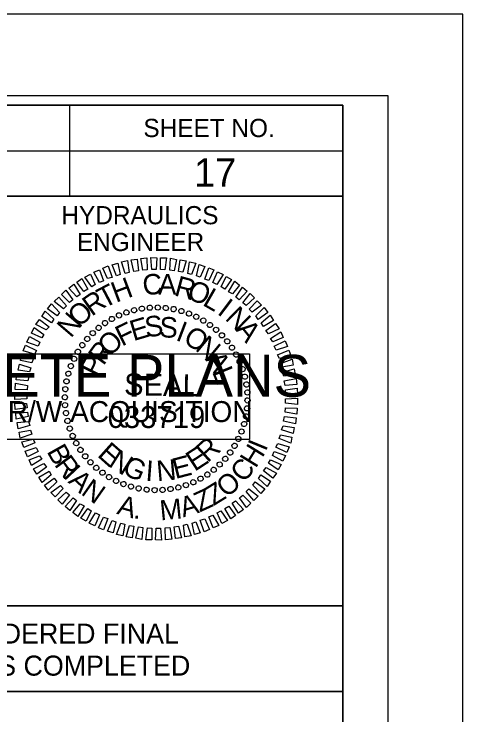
# Model space of a CAD drawing. Extents: x 1779926 to 1781626, y 618464 to 619564.
# Drawn here: x 1781502.8 to 1781626, y 619371.7 to 619564.2 of the extents above; entities that cross this region are included whole.
import ezdxf

# ---------------------------------------------------------------- set-up
doc = ezdxf.new("R2010")
doc.units = 0
for name, color, linetype in [('Old_Level_58', 7, 'Continuous'), ('Sheet Data Field CELL', 7, 'Continuous'), ('Sheet Plot Border Inside CELL', 7, 'Continuous'), ('Sheet Plot Border Outside CELL', 7, 'Continuous'), ('Sheet Professional Seal CELL', 7, 'Continuous'), ('Sheet Profile CELL', 7, 'Continuous'), ('Sheet Profile Grid Major CELL', 7, 'Continuous'), ('Sheet Profile Grid Minor CELL', 7, 'Continuous'), ('Sheet Sticker Exception Certification CELL', 7, 'Continuous'), ('Sheet Sticker Incomplete CELL', 7, 'Continuous')]:
    doc.layers.add(name, color=color, linetype=linetype)

msp = doc.modelspace()

# ---------------------------------------------------------------- linework, layer by layer
at = {"layer": 'Old_Level_58'}
for points in [[(1781392.9, 619378.14), (1781592.96, 619378.14), (1781592.96, 619314.19), (1781392.9, 619314.19)], [(1781392.96, 619378.14), (1781592.96, 619378.14), (1781592.96, 619314.19), (1781392.96, 619314.19)]]:
    msp.add_lwpolyline(points, close=True, dxfattribs=at)
at = {"layer": 'Sheet Plot Border Inside CELL'}
msp.add_lwpolyline([(1779938.96, 618486.64), (1781605.46, 618486.64), (1781605.46, 619541.74), (1779938.96, 619541.74)], close=True, dxfattribs=at)
at = {"layer": 'Sheet Plot Border Outside CELL'}
msp.add_lwpolyline([(1779925.96, 618464.19), (1781625.96, 618464.19), (1781625.96, 619564.19), (1779925.96, 619564.19)], close=True, dxfattribs=at)
at = {"layer": 'Sheet Professional Seal CELL'}
for p, q in [((1781535.68, 619482.87), (1781535.68, 619482.87)), ((1781537.88, 619483.27), (1781537.88, 619483.27)), ((1781540.03, 619483.57), (1781540.03, 619483.57)), ((1781542.23, 619483.62), (1781542.23, 619483.62)), ((1781544.43, 619483.47), (1781544.43, 619483.47)), ((1781546.58, 619483.12), (1781546.58, 619483.12)), ((1781548.68, 619482.67), (1781548.68, 619482.67)), ((1781529.63, 619480.47), (1781529.63, 619480.47)), ((1781531.58, 619481.47), (1781531.58, 619481.47)), ((1781533.58, 619482.27), (1781533.58, 619482.27)), ((1781550.78, 619481.97), (1781550.78, 619481.97)), ((1781552.78, 619481.07), (1781552.78, 619481.07)), ((1781527.73, 619479.32), (1781527.73, 619479.32)), ((1781554.73, 619480.07), (1781554.73, 619480.07)), ((1781556.53, 619478.82), (1781556.53, 619478.82)), ((1781524.33, 619476.57), (1781524.33, 619476.57)), ((1781525.98, 619478.07), (1781525.98, 619478.07)), ((1781558.28, 619477.47), (1781558.28, 619477.47)), ((1781522.83, 619475.02), (1781522.83, 619475.02)), ((1781559.83, 619475.97), (1781559.83, 619475.97)), ((1781521.48, 619473.27), (1781521.48, 619473.27)), ((1781561.33, 619474.32), (1781561.33, 619474.32)), ((1781520.23, 619471.47), (1781520.23, 619471.47)), ((1781562.58, 619472.57), (1781562.58, 619472.57)), ((1781519.23, 619469.52), (1781519.23, 619469.52)), ((1781563.73, 619470.67), (1781563.73, 619470.67)), ((1781518.33, 619467.52), (1781518.33, 619467.52)), ((1781564.73, 619468.72), (1781564.73, 619468.72)), ((1781517.63, 619465.42), (1781517.63, 619465.42)), ((1781565.53, 619466.72), (1781565.53, 619466.72)), ((1781517.18, 619463.32), (1781517.18, 619463.32)), ((1781566.13, 619464.62), (1781566.13, 619464.62)), ((1781516.83, 619461.17), (1781516.83, 619461.17)), ((1781566.53, 619462.42), (1781566.53, 619462.42)), ((1781566.83, 619460.27), (1781566.83, 619460.27)), ((1781516.68, 619458.97), (1781516.68, 619458.97)), ((1781541.78, 619458.52), (1781541.78, 619458.52)), ((1781566.88, 619458.07), (1781566.88, 619458.07)), ((1781516.73, 619456.77), (1781516.73, 619456.77)), ((1781566.73, 619455.87), (1781566.73, 619455.87)), ((1781517.03, 619454.62), (1781517.03, 619454.62)), ((1781566.38, 619453.72), (1781566.38, 619453.72)), ((1781517.43, 619452.42), (1781517.43, 619452.42)), ((1781565.93, 619451.62), (1781565.93, 619451.62)), ((1781518.03, 619450.32), (1781518.03, 619450.32)), ((1781518.83, 619448.32), (1781518.83, 619448.32)), ((1781565.23, 619449.52), (1781565.23, 619449.52)), ((1781519.83, 619446.37), (1781519.83, 619446.37)), ((1781564.33, 619447.52), (1781564.33, 619447.52)), ((1781520.98, 619444.47), (1781520.98, 619444.47)), ((1781563.33, 619445.57), (1781563.33, 619445.57)), ((1781522.23, 619442.72), (1781522.23, 619442.72)), ((1781560.73, 619442.02), (1781560.73, 619442.02)), ((1781562.08, 619443.77), (1781562.08, 619443.77)), ((1781523.73, 619441.07), (1781523.73, 619441.07)), ((1781559.23, 619440.47), (1781559.23, 619440.47)), ((1781525.28, 619439.57), (1781525.28, 619439.57)), ((1781527.03, 619438.22), (1781527.03, 619438.22)), ((1781557.58, 619438.97), (1781557.58, 619438.97)), ((1781528.83, 619436.97), (1781528.83, 619436.97)), ((1781553.93, 619436.57), (1781553.93, 619436.57)), ((1781555.83, 619437.72), (1781555.83, 619437.72)), ((1781530.78, 619435.97), (1781530.78, 619435.97)), ((1781532.78, 619435.07), (1781532.78, 619435.07)), ((1781534.88, 619434.37), (1781534.88, 619434.37)), ((1781549.98, 619434.77), (1781549.98, 619434.77)), ((1781551.98, 619435.57), (1781551.98, 619435.57)), ((1781536.98, 619433.92), (1781536.98, 619433.92)), ((1781539.13, 619433.57), (1781539.13, 619433.57)), ((1781541.33, 619433.42), (1781541.33, 619433.42)), ((1781543.53, 619433.47), (1781543.53, 619433.47)), ((1781545.68, 619433.77), (1781545.68, 619433.77)), ((1781547.88, 619434.17), (1781547.88, 619434.17))]:
    msp.add_line(p, q, dxfattribs=at)
for points in [[(1781533.28, 619492.97), (1781532.23, 619496.12), (1781533.93, 619496.47), (1781534.33, 619493.22)], [(1781535.68, 619493.52), (1781534.88, 619496.72), (1781536.53, 619496.87), (1781536.88, 619493.67)], [(1781538.08, 619493.82), (1781537.53, 619497.02), (1781539.23, 619497.22), (1781539.28, 619493.97)], [(1781540.58, 619494.07), (1781540.33, 619497.32), (1781541.98, 619497.27), (1781541.78, 619494.02)], [(1781542.98, 619494.02), (1781542.98, 619497.27), (1781544.63, 619497.22), (1781544.18, 619493.97)], [(1781545.48, 619493.87), (1781545.68, 619497.12), (1781547.33, 619496.82), (1781546.68, 619493.67)], [(1781547.88, 619493.47), (1781548.33, 619496.67), (1781549.98, 619496.42), (1781549.08, 619493.32)], [(1781550.43, 619492.92), (1781550.93, 619496.17), (1781552.63, 619495.77), (1781551.48, 619492.67)], [(1781526.23, 619490.47), (1781524.63, 619493.27), (1781526.18, 619493.97), (1781527.33, 619490.92)], [(1781528.43, 619491.52), (1781527.13, 619494.42), (1781528.63, 619495.02), (1781529.68, 619491.82)], [(1781530.88, 619492.32), (1781529.73, 619495.32), (1781531.28, 619495.77), (1781531.93, 619492.67)], [(1781552.83, 619492.27), (1781553.58, 619495.37), (1781555.13, 619494.87), (1781553.88, 619491.92)], [(1781555.08, 619491.37), (1781556.23, 619494.52), (1781557.63, 619493.92), (1781556.23, 619491.02)], [(1781524.08, 619489.27), (1781522.23, 619491.97), (1781523.78, 619492.77), (1781525.03, 619489.87)], [(1781557.33, 619490.42), (1781558.58, 619493.37), (1781560.13, 619492.67), (1781558.43, 619489.87)], [(1781559.63, 619489.27), (1781560.98, 619492.12), (1781562.48, 619491.27), (1781560.58, 619488.67)], [(1781521.88, 619488.02), (1781520.03, 619490.57), (1781521.33, 619491.52), (1781522.98, 619488.62)], [(1781561.58, 619487.92), (1781563.33, 619490.82), (1781564.63, 619489.77), (1781562.68, 619487.32)], [(1781517.98, 619484.97), (1781515.78, 619487.17), (1781516.98, 619488.37), (1781518.93, 619485.67)], [(1781519.98, 619486.52), (1781517.83, 619488.92), (1781519.18, 619489.97), (1781520.93, 619487.17)], [(1781563.63, 619486.42), (1781565.48, 619489.17), (1781566.78, 619488.07), (1781564.58, 619485.72)], [(1781516.33, 619483.22), (1781513.78, 619485.27), (1781515.03, 619486.42), (1781517.13, 619484.02)], [(1781565.53, 619484.87), (1781567.58, 619487.47), (1781568.78, 619486.27), (1781566.48, 619484.12)], [(1781514.58, 619481.32), (1781511.98, 619483.27), (1781513.08, 619484.57), (1781515.28, 619482.22)], [(1781567.33, 619483.12), (1781569.48, 619485.47), (1781570.68, 619484.27), (1781568.08, 619482.32)], [(1781513.08, 619479.42), (1781510.38, 619481.12), (1781511.33, 619482.57), (1781513.73, 619480.37)], [(1781569.08, 619481.32), (1781571.38, 619483.57), (1781572.43, 619482.22), (1781569.78, 619480.32)], [(1781570.58, 619479.37), (1781573.03, 619481.47), (1781573.98, 619480.02), (1781571.18, 619478.42)], [(1781511.58, 619477.42), (1781508.78, 619478.92), (1781509.78, 619480.32), (1781512.38, 619478.32)], [(1781571.88, 619477.32), (1781574.53, 619479.22), (1781575.48, 619477.72), (1781572.58, 619476.32)], [(1781510.38, 619475.27), (1781507.53, 619476.52), (1781508.28, 619478.07), (1781510.98, 619476.22)], [(1781573.18, 619475.12), (1781575.98, 619476.87), (1781576.63, 619475.32), (1781573.78, 619474.17)], [(1781509.38, 619472.97), (1781506.28, 619474.12), (1781507.03, 619475.67), (1781509.88, 619474.07)], [(1781508.38, 619470.77), (1781505.28, 619471.67), (1781505.93, 619473.22), (1781508.93, 619471.82)], [(1781574.18, 619472.97), (1781577.13, 619474.47), (1781577.78, 619472.87), (1781574.68, 619471.87)], [(1781575.08, 619470.62), (1781578.13, 619471.92), (1781578.68, 619470.37), (1781575.58, 619469.57)], [(1781507.63, 619468.37), (1781504.53, 619469.02), (1781504.88, 619470.67), (1781508.03, 619469.42)], [(1781575.88, 619468.22), (1781579.08, 619469.37), (1781579.38, 619467.72), (1781576.23, 619467.17)], [(1781506.98, 619465.97), (1781503.88, 619466.37), (1781504.23, 619468.07), (1781507.38, 619467.02)], [(1781506.58, 619463.42), (1781503.38, 619463.72), (1781503.58, 619465.42), (1781506.83, 619464.62)], [(1781576.48, 619465.82), (1781579.63, 619466.77), (1781579.93, 619465.07), (1781576.78, 619464.77)], [(1781576.93, 619463.42), (1781580.18, 619464.12), (1781580.33, 619462.42), (1781577.13, 619462.22)], [(1781506.33, 619461.02), (1781503.08, 619461.12), (1781503.18, 619462.77), (1781506.43, 619462.22)], [(1781577.23, 619461.02), (1781580.48, 619461.42), (1781580.58, 619459.72), (1781577.33, 619459.82)], [(1781506.28, 619458.52), (1781503.03, 619458.37), (1781503.03, 619460.07), (1781506.28, 619459.72)], [(1781506.33, 619456.02), (1781503.08, 619455.62), (1781502.98, 619457.32), (1781506.23, 619457.22)], [(1781577.28, 619458.52), (1781580.53, 619458.67), (1781580.53, 619456.97), (1781577.28, 619457.32)], [(1781577.23, 619456.02), (1781580.48, 619455.92), (1781580.38, 619454.27), (1781577.13, 619454.82)], [(1781506.63, 619453.62), (1781503.38, 619452.92), (1781503.23, 619454.62), (1781506.43, 619454.82)], [(1781576.98, 619453.62), (1781580.18, 619453.32), (1781579.98, 619451.62), (1781576.73, 619452.42)], [(1781507.08, 619451.22), (1781503.93, 619450.27), (1781503.63, 619451.97), (1781506.78, 619452.27)], [(1781507.68, 619448.82), (1781504.48, 619447.67), (1781504.18, 619449.32), (1781507.33, 619449.87)], [(1781576.58, 619451.07), (1781579.68, 619450.67), (1781579.33, 619448.97), (1781576.18, 619450.02)], [(1781575.93, 619448.67), (1781579.03, 619448.02), (1781578.68, 619446.37), (1781575.53, 619447.62)], [(1781508.48, 619446.42), (1781505.43, 619445.12), (1781504.88, 619446.67), (1781507.98, 619447.47)], [(1781575.18, 619446.27), (1781578.28, 619445.37), (1781577.63, 619443.82), (1781574.63, 619445.22)], [(1781509.38, 619444.07), (1781506.43, 619442.57), (1781505.78, 619444.17), (1781508.88, 619445.17)], [(1781574.18, 619444.07), (1781577.28, 619442.92), (1781576.53, 619441.37), (1781573.68, 619442.97)], [(1781510.38, 619441.92), (1781507.58, 619440.17), (1781506.93, 619441.72), (1781509.78, 619442.87)], [(1781511.68, 619439.72), (1781509.03, 619437.82), (1781508.08, 619439.32), (1781510.98, 619440.72)], [(1781573.18, 619441.77), (1781576.03, 619440.52), (1781575.28, 619438.97), (1781572.58, 619440.82)], [(1781512.98, 619437.67), (1781510.53, 619435.57), (1781509.58, 619437.02), (1781512.38, 619438.62)], [(1781571.98, 619439.62), (1781574.78, 619438.12), (1781573.78, 619436.72), (1781571.18, 619438.72)], [(1781514.48, 619435.72), (1781512.18, 619433.47), (1781511.13, 619434.82), (1781513.78, 619436.72)], [(1781570.48, 619437.62), (1781573.18, 619435.92), (1781572.23, 619434.47), (1781569.83, 619436.67)], [(1781516.23, 619433.92), (1781514.08, 619431.57), (1781512.88, 619432.77), (1781515.48, 619434.72)], [(1781568.98, 619435.72), (1781571.58, 619433.77), (1781570.48, 619432.47), (1781568.28, 619434.82)], [(1781518.03, 619432.17), (1781515.98, 619429.57), (1781514.78, 619430.77), (1781517.08, 619432.92)], [(1781567.23, 619433.82), (1781569.78, 619431.77), (1781568.53, 619430.62), (1781566.43, 619433.02)], [(1781519.93, 619430.62), (1781518.08, 619427.87), (1781516.78, 619428.97), (1781518.98, 619431.32)], [(1781563.58, 619430.52), (1781565.73, 619428.12), (1781564.38, 619427.07), (1781562.63, 619429.87)], [(1781565.58, 619432.07), (1781567.78, 619429.87), (1781566.58, 619428.67), (1781564.63, 619431.37)], [(1781521.98, 619429.12), (1781520.23, 619426.22), (1781518.93, 619427.27), (1781520.88, 619429.72)], [(1781561.68, 619429.02), (1781563.53, 619426.47), (1781562.23, 619425.52), (1781560.58, 619428.42)], [(1781523.93, 619427.77), (1781522.58, 619424.92), (1781521.08, 619425.77), (1781522.98, 619428.37)], [(1781526.23, 619426.62), (1781524.98, 619423.67), (1781523.43, 619424.37), (1781525.13, 619427.17)], [(1781557.33, 619426.57), (1781558.93, 619423.77), (1781557.38, 619423.07), (1781556.23, 619426.12)], [(1781559.48, 619427.77), (1781561.33, 619425.07), (1781559.78, 619424.27), (1781558.53, 619427.17)], [(1781528.48, 619425.67), (1781527.33, 619422.52), (1781525.93, 619423.12), (1781527.33, 619426.02)], [(1781530.73, 619424.77), (1781529.98, 619421.67), (1781528.43, 619422.17), (1781529.68, 619425.12)], [(1781552.68, 619424.72), (1781553.83, 619421.72), (1781552.28, 619421.27), (1781551.63, 619424.37)], [(1781555.13, 619425.52), (1781556.43, 619422.62), (1781554.93, 619422.02), (1781553.88, 619425.22)], [(1781533.13, 619424.12), (1781532.63, 619420.87), (1781530.93, 619421.27), (1781532.08, 619424.37)], [(1781535.68, 619423.57), (1781535.23, 619420.37), (1781533.58, 619420.62), (1781534.48, 619423.72)], [(1781538.08, 619423.17), (1781537.88, 619419.92), (1781536.23, 619420.22), (1781536.88, 619423.37)], [(1781540.58, 619423.02), (1781540.58, 619419.77), (1781538.93, 619419.82), (1781539.38, 619423.07)], [(1781542.98, 619422.97), (1781543.23, 619419.72), (1781541.58, 619419.77), (1781541.78, 619423.02)], [(1781545.48, 619423.22), (1781546.03, 619420.02), (1781544.33, 619419.82), (1781544.28, 619423.07)], [(1781547.88, 619423.52), (1781548.68, 619420.32), (1781547.03, 619420.17), (1781546.68, 619423.37)], [(1781550.28, 619424.07), (1781551.33, 619420.92), (1781549.63, 619420.57), (1781549.23, 619423.82)]]:
    msp.add_lwpolyline(points, close=True, dxfattribs=at)
for centre, major_axis in [((1781540.03, 619483.54), (-0.05, 0.718)), ((1781542.22, 619483.59), (0.013, 0.72)), ((1781533.61, 619482.23), (-0.234, 0.681)), ((1781535.71, 619482.85), (-0.174, 0.699)), ((1781537.85, 619483.29), (-0.113, 0.711)), ((1781544.4, 619483.46), (0.075, 0.716)), ((1781546.56, 619483.14), (0.137, 0.707)), ((1781548.69, 619482.62), (0.198, 0.692)), ((1781550.77, 619481.93), (0.258, 0.672)), ((1781529.62, 619480.45), (-0.349, 0.63)), ((1781531.58, 619481.43), (-0.293, 0.658)), ((1781552.77, 619481.06), (0.316, 0.647)), ((1781554.69, 619480.01), (0.371, 0.617)), ((1781525.99, 619478.01), (-0.453, 0.56)), ((1781527.75, 619479.31), (-0.403, 0.597)), ((1781556.52, 619478.81), (0.423, 0.582)), ((1781524.36, 619476.56), (-0.5, 0.518)), ((1781558.23, 619477.44), (0.472, 0.543)), ((1781559.82, 619475.94), (0.518, 0.5)), ((1781522.85, 619474.97), (-0.543, 0.472)), ((1781561.27, 619474.3), (0.56, 0.453)), ((1781521.49, 619473.26), (-0.582, 0.423)), ((1781562.57, 619472.54), (0.597, 0.403)), ((1781520.28, 619471.43), (-0.617, 0.371)), ((1781563.71, 619470.68), (0.63, 0.349)), ((1781519.24, 619469.51), (-0.647, 0.316)), ((1781564.69, 619468.72), (0.658, 0.293)), ((1781518.36, 619467.5), (-0.672, 0.258)), ((1781565.49, 619466.68), (0.681, 0.234)), ((1781517.67, 619465.43), (-0.692, 0.198)), ((1781566.11, 619464.58), (0.699, 0.174)), ((1781517.16, 619463.3), (-0.707, 0.137)), ((1781566.55, 619462.44), (0.711, 0.113)), ((1781516.83, 619461.14), (-0.716, 0.075)), ((1781516.7, 619458.95), (-0.72, 0.013)), ((1781566.8, 619460.27), (0.718, 0.05)), ((1781516.76, 619456.77), (-0.718, -0.05)), ((1781566.85, 619458.08), (0.72, -0.013)), ((1781566.72, 619455.89), (0.716, -0.075)), ((1781517.01, 619454.59), (-0.711, -0.113)), ((1781566.4, 619453.73), (0.707, -0.137)), ((1781517.44, 619452.45), (-0.699, -0.174)), ((1781565.89, 619451.6), (0.692, -0.198)), ((1781518.06, 619450.35), (-0.681, -0.234)), ((1781565.19, 619449.53), (0.672, -0.258)), ((1781518.87, 619448.32), (-0.658, -0.293)), ((1781564.32, 619447.52), (0.647, -0.316)), ((1781519.84, 619446.36), (-0.63, -0.349)), ((1781563.28, 619445.6), (0.617, -0.371)), ((1781520.99, 619444.49), (-0.597, -0.403)), ((1781562.07, 619443.77), (0.582, -0.423)), ((1781522.29, 619442.73), (-0.56, -0.453)), ((1781560.71, 619442.06), (0.543, -0.472)), ((1781523.74, 619441.09), (-0.518, -0.5)), ((1781525.32, 619439.59), (-0.472, -0.543)), ((1781559.2, 619440.48), (0.5, -0.518)), ((1781527.04, 619438.23), (-0.423, -0.582)), ((1781555.8, 619437.72), (0.403, -0.597)), ((1781557.56, 619439.03), (0.453, -0.56)), ((1781528.86, 619437.02), (-0.371, -0.617)), ((1781530.78, 619435.97), (-0.316, -0.647)), ((1781551.98, 619435.6), (0.293, -0.658)), ((1781553.94, 619436.58), (0.349, -0.63)), ((1781532.79, 619435.1), (-0.258, -0.672)), ((1781534.86, 619434.41), (-0.198, -0.692)), ((1781536.99, 619433.9), (-0.137, -0.707)), ((1781539.16, 619433.57), (-0.075, -0.716)), ((1781543.53, 619433.5), (0.05, -0.718)), ((1781545.7, 619433.75), (0.113, -0.711)), ((1781547.84, 619434.18), (0.174, -0.699)), ((1781549.94, 619434.8), (0.234, -0.681)), ((1781541.34, 619433.44), (-0.013, -0.72))]:
    msp.add_ellipse(centre, major_axis=major_axis, ratio=0.999708, dxfattribs=at)
at = {"layer": 'Sheet Profile CELL'}
for p, q in [((1781517.96, 619539.14), (1781517.96, 619514.14)), ((1781392.91, 619526.64), (1781592.96, 619526.64))]:
    msp.add_line(p, q, dxfattribs=at)
for points in [[(1781592.96, 619539.19), (1780092.96, 619539.19), (1780092.96, 618489.19), (1781592.96, 618489.19)], [(1781392.91, 619539.19), (1781592.96, 619539.19), (1781592.96, 619514.14), (1781392.91, 619514.14)], [(1781492.96, 619514.14), (1781592.96, 619514.14), (1781592.96, 619401.64), (1781492.96, 619401.64)]]:
    msp.add_lwpolyline(points, close=True, dxfattribs=at)
at = {"layer": 'Sheet Profile Grid Major CELL'}
msp.add_lwpolyline([(1781542.96, 619314.19), (1781542.96, 619039.19), (1781592.96, 619039.19), (1781592.96, 619389.19)], dxfattribs=at)
at = {"layer": 'Sheet Sticker Exception Certification CELL'}
for p, q in [((1781392.91, 619401.64), (1781592.95, 619401.64)), ((1781392.91, 619401.64), (1781592.95, 619401.64)), ((1781592.95, 619401.63), (1781592.95, 619378.13)), ((1781592.95, 619401.63), (1781592.95, 619378.13)), ((1781592.95, 619378.14), (1781392.91, 619378.14)), ((1781592.95, 619378.14), (1781392.91, 619378.14))]:
    msp.add_line(p, q, dxfattribs=at)
at = {"layer": 'Sheet Sticker Incomplete CELL'}
msp.add_lwpolyline([(1781420.37, 619447.38), (1781420.37, 619470.88), (1781567.37, 619470.88), (1781567.37, 619447.38)], close=True, dxfattribs=at)

# ---------------------------------------------------------------- texts
at = {"layer": 'Sheet Data Field CELL'}
msp.add_text('17', height=7.75, dxfattribs=at).set_placement((1781552.18, 619516.8))
at = {"layer": 'Sheet Professional Seal CELL'}
for s, height, rotation, p in [('C', 5.64, 6.2199, (1781538.33, 619486.87)), ('A', 5.64, 359.0203, (1781542.28, 619487.17)), ('R', 5.64, 344.6211, (1781546.48, 619486.97)), ('T', 5.64, 27.8198, (1781527.48, 619483.22)), ('H', 5.64, 20.6195, (1781530.73, 619484.87)), ('O', 5.64, 337.4212, (1781549.83, 619486.22)), ('L', 5.64, 330.2209, (1781554.23, 619484.37)), ('R', 5.64, 35.0205, (1781524.08, 619481.02)), ('O', 5.64, 42.2217, (1781520.63, 619477.92)), ('I', 5.64, 323.0201, (1781558.28, 619481.97)), ('N', 5.64, 49.4235, (1781518.33, 619475.02)), ('N', 5.64, 315.8189, (1781560.43, 619480.42)), ('E', 5.64, 16.6111, (1781535.53, 619474.32)), ('S', 5.64, 7.2556, (1781538.98, 619475.37)), ('S', 5.64, 357.9004, (1781542.58, 619475.42)), ('F', 5.64, 25.967, (1781532.33, 619472.82)), ('I', 5.64, 339.1896, (1781546.88, 619474.72)), ('A', 5.64, 308.6172, (1781563.38, 619477.47)), ('O', 5.64, 44.6812, (1781529.03, 619469.87)), ('O', 5.64, 329.8335, (1781548.88, 619474.02)), ('N', 5.64, 320.4766, (1781552.23, 619472.02)), ('R', 5.64, 54.0397, (1781527.28, 619467.42)), ('P', 5.64, 63.3989, (1781525.68, 619464.22)), ('A', 5.64, 301.7603, (1781555.08, 619469.42)), ('L', 5.64, 292.4008, (1781557.03, 619465.97)), ('SEAL', 5.998, 359, (1781532.93, 619459.52)), ('E', 5.64, 318.2769, (1781525.38, 619442.87)), ('R', 5.64, 42.4814, (1781555.88, 619440.77)), ('N', 5.64, 327.634, (1781528.38, 619440.17)), ('E', 5.64, 33.1241, (1781552.33, 619438.42)), ('G', 5.64, 336.9902, (1781532.18, 619437.92)), ('N', 5.64, 5.0564, (1781542.08, 619435.87)), ('E', 5.64, 14.4118, (1781547.03, 619436.47)), ('I', 5.64, 355.7012, (1781538.73, 619436.02))]:
    msp.add_text(s, height=height, rotation=rotation, dxfattribs=at).set_placement(p)
at = {"layer": 'Sheet Profile CELL'}
for s, p in [('SHEET NO.', (1781538.27, 619530.4)), ('HYDRAULICS', (1781515.77, 619506.45)), ('ENGINEER', (1781520.02, 619499.1))]:
    msp.add_text(s, height=5, dxfattribs=at).set_placement(p)
at = {"layer": 'Sheet Profile Grid Minor CELL'}
msp.add_text('033719', height=5.998, dxfattribs=at).set_placement((1781528.46, 619450.51))
for s, rotation, p in [('B', 299.1529, (1781511.63, 619444.08)), ('H', 58.3478, (1781569.09, 619439.24)), ('I', 67.5926, (1781571.83, 619443.88)), ('R', 306.2797, (1781513.65, 619440.45)), ('C', 49.4751, (1781565.79, 619435.26)), ('I', 313.2061, (1781516.04, 619437.19)), ('A', 316.7266, (1781517.4, 619435.65)), ('N', 324.9124, (1781520.9, 619432.41)), ('O', 38.7706, (1781561.05, 619431.2)), ('Z', 31.6438, (1781557.51, 619429.02)), ('Z', 24.517, (1781553.73, 619427.3)), ('A', 344.2893, (1781530.75, 619426.96)), ('M', 5.6554, (1781543, 619425.11)), ('A', 16.3312, (1781549.17, 619425.92)), ('.', 352.4751, (1781535.35, 619425.71))]:
    msp.add_text(s, height=5.5, rotation=rotation, dxfattribs=at).set_placement(p)
at = {"layer": 'Sheet Sticker Exception Certification CELL'}
for s, p in [('DOCUMENT NOT CONSIDERED FINAL', (1781413.98, 619391.3)), ('DOCUMENT NOT CONSIDERED FINAL', (1781413.98, 619391.3)), ('UNLESS ALL SIGNATURES COMPLETED', (1781408.91, 619382.5)), ('UNLESS ALL SIGNATURES COMPLETED', (1781408.91, 619382.5))]:
    msp.add_text(s, height=5.5, dxfattribs=at).set_placement(p)
at = {"layer": 'Sheet Sticker Incomplete CELL'}
for s, height, p in [('INCOMPLETE PLANS', 11.52, (1781429.32, 619459.08)), ('DO NOT USE FOR R/W ACQUISITION', 5.76, (1781432.57, 619452.13))]:
    msp.add_text(s, height=height, dxfattribs=at).set_placement(p)

doc.saveas('drawing.dxf')
